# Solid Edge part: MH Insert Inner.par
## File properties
Title: MH Insert Inner
Author: Dan
Template: Metric Part.par
Last saved by: Dan
Revision: 5
Application: Solid Edge
Accuracy: 0.990
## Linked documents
FH Insert Inner.par
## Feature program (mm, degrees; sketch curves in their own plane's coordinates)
part copy "CopiedPart_1"
delete holes assoc c "unnamed DeleteHolesAssocC 1"
delete faces "unnamed DeleteFaces 1"
delete faces "unnamed DeleteFaces 2"
sketch for "Hole_1" plane through (0, 0, -36) normal (0, 0, -1) x-axis (-1, 0, 0)
  hole centre (0, 0) bore radius 12.5
hole "Hole_1" diameter 25 through  VBottomAngle = 118 deg
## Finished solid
Body 1: solid body, 10 faces, 10 edges, 0 vertices.
  Faces by surface: plane 5, cylinder 3, cone 2
  Edges by curve: circle 10
Bounding box of the edges (mm): 44.000 x 44.000 x 30.000, from (-22, -22, -36) to (22, 22, -6).
Cylindrical faces by radius (mm): R12.5 x1, R18.8116 x1, R22 x1
Conical faces (half-angle, radius in mm at the cone's reference point): 1 deg R18.3793 x1, 2 deg R17.0012 x1
Planar faces by outward normal: +z 4, -z 1
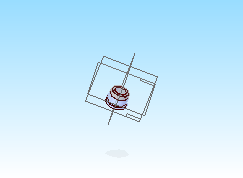
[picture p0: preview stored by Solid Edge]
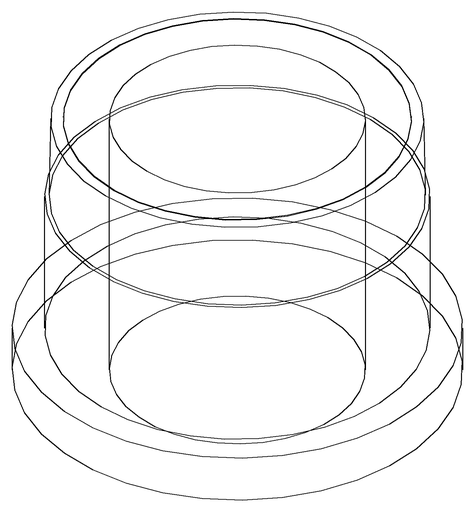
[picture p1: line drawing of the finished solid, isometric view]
